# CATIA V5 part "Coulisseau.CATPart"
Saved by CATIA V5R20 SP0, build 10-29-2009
Part number: Coulisseau
Publications: "LongueurCoulisseau"
Bounding box of the stored display mesh (mm): x 16 to 22, y 3.413 to 110, z 34.355 to 85.778
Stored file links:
  C:\Users\Thinkmotion2\Desktop\Pack 1\Retouchés\IAO_2010_1386_abergami\abergami_catiaInitial\ObjetsInitials\Coulisseau.CATPart
  C:\Users\Thinkmotion2\Desktop\Pack 1\Retouchés\IAO_2010_1386_abergami\abergami_catiaInitial\ObjetsInitials\Product2.CATProduct
  C:\Users\Thinkmotion2\Desktop\Pack 1\Retouchés\IAO_2010_1386_abergami\abergami_catiaInitial\ObjetsInitials\NewExcentrique.CATPart
  C:\Users\Thinkmotion2\Desktop\Pack 1\Retouchés\IAO_2010_1386_abergami\abergami_catiaInitial\ObjetsInitials\Squelettedebase.CATPart
  C:\Users\Thinkmotion2\Desktop\Pack 1\Retouchés\IAO_2010_1386_abergami\abergami_catiaInitial\ObjetsInitials\Doigt.CATPart
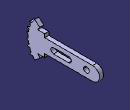
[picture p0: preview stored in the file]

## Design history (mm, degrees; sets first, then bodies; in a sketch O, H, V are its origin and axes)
Parameters
  LongueurCoulisseau = 70 mm
External parameters (linked from other documents)
  External.largeurrainure = 18 mm
  External.EpaisseurCoulisseau = 6 mm
  External.DiametreDoigtExcentrique = 8 mm
  External.DiametreDoigtBati = 8 mm
  External.entraxeDoigtAC = 36 mm
  External.EntraxeAB = 9 mm
Set1
  DatumSurface1: linked copy from another document
  Point1 to Point5: linked copy from another document
Body1 (main body)
  Sketch1 on face of DatumSurface1, origin (16, 0, 0), H (0, 1, 0), V (0, 0, 1)
    arc A1 centre (100, 60) radius 10 from (100, 50) to (100, 70) ccw
    point P1 (100, 60)
    line L1 (100, 70) -> (30, 70)
    point P4 (30, 70)
    line L2 (100, 50) -> (30, 50)
    point P5 (30, 50)
    line L3 (30, 45) -> (30, 50)
    point P6 (30, 45)
    point P7 (30, 75)
    reference projected point E1 (100, 60) from Point3
    reference projected point E2 (100, 60) from Point3
    line L4 (30, 75) -> (20, 75)
    point P8 (20, 75)
    line L5 (30, 45) -> (20, 45)
    point P9 (20, 45)
    arc A2 centre (50, 60) radius 33.541 from (22.7561, 79.5645) to (20, 75) ccw
    line L6 (16.3377, 35.2443) -> (23.1724, 40.9541)
    line L7 (22.7561, 79.5645) -> (15.384, 85.7776)
    arc A3 centre (47.903, 63.6125) radius 33.541 from (20, 45) to (23.1724, 40.9541) ccw
    line L8 (30, 70) -> (30, 75)
    arc A4 centre (45.9702, 60) radius 40 from (15.384, 85.7776) to (11.2225, 79.8141) ccw
    point P14 (45.9702, 60)
    point P15 (15.273, 34.3547)
    line L9 (15.273, 34.3547) -> (16.3377, 35.2443)
    line L10 (6.0167, 58.0706) -> (3.4138, 55.896)
    line L11 (3.4138, 55.896) -> (6.3223, 54.704)
    point P18 (6.3223, 54.704)
    line L12 (6.0354, 62.2833) -> (3.4126, 64.1749)
    point P19 (6.0354, 62.2833)
    line L13 (3.4126, 64.1749) -> (6.3314, 65.3633)
    line L14 (7.0442, 69.2069) -> (4.5538, 72.0604)
    point P22 (7.0442, 69.2069)
    line L15 (4.5538, 72.0604) -> (8.0484, 72.7254)
    line L16 (9.4614, 76.3435) -> (8.0484, 79.8141)
    point P25 (9.4614, 76.3435)
    line L17 (8.0484, 79.8141) -> (11.2225, 79.8141)
    line L18 (7.0442, 50.7931) -> (4.5538, 47.34)
    line L19 (4.5538, 47.34) -> (8.2161, 46.7852)
    point P30 (8.2161, 46.7852)
    line L20 (10.2902, 41.9185) -> (8.0484, 38.81)
    line L21 (8.0484, 38.81) -> (12.044, 38.81)
    point P33 (12.044, 38.81)
    arc A5 centre (45.9702, 60) radius 40 from (12.044, 38.81) to (15.273, 34.3547) ccw
    arc A6 centre (45.9702, 60) radius 40 from (8.2161, 46.7852) to (10.2902, 41.9185) ccw
    arc A7 centre (45.9702, 60) radius 40 from (6.3223, 54.704) to (7.0442, 50.7931) ccw
    arc A8 centre (45.9702, 60) radius 40 from (6.0354, 62.2833) to (6.0167, 58.0706) ccw
    arc A9 centre (45.9702, 60) radius 40 from (7.0442, 69.2069) to (6.3314, 65.3633) ccw
    arc A10 centre (45.9702, 60) radius 40 from (9.4614, 76.3435) to (8.0484, 72.7254) ccw
    distance P5 P6 = 5
    length L1 = 70 {= LongueurCoulisseau}
    radius A1 = 10
    distance E1 L2 = 10
    distance P7 L1 = 5
    distance P1 E2 = 0
    length L5 = 10
    length L2 = 70
    angle L7 L6 = 80
    distance P6 P7 = 30
    distance A2 P4 = 11.1803
    distance P14 L2 = 10
    radius A4 = 40
    horizontal: L1 H, L4 H, L5 H, L17 H, L21 H
    tangency: L2 A1
    vertical: L3 V, L8 V
    coincidence: L3 L8, P14 L7, P14 L6, P15 L6, P18 A4, L11 P6, P19 A4, L12 P6, L13 P7, P22 A4, L15 P8, P25 A4, P30 A4, L19 P9, P33 A4, A4 A5, A4 A6, A4 A7, A4 A8, A4 A9, A4 A10
    parallelism: L9 L6
  Pad1: profile Sketch1, direction (1, 0, 0), length 6 {= External.EpaisseurCoulisseau}
  Sketch2 on end face of Pad1, origin (22, 0, 0), H (0, 1, 0), V (0, 0, 1)
    circle A1 centre (91, 60) radius 4
    point P1 (91, 60)
    reference projected point E1 (91, 60) from Point4
    arc A2 centre (65, 60) radius 4 from (65, 56) to (65, 64) ccw
    point P2 (65, 60)
    arc A3 centre (43, 60) radius 4 from (43, 64) to (43, 56) ccw
    line L1 (65, 64) -> (43, 64)
    line L2 (65, 56) -> (43, 56)
    radius A1 = 4 {= External.DiametreDoigtExcentrique /2}
    distance E1 P1 = 0
    radius A3 = 4 {= External.DiametreDoigtBati /2}
    radius A2 = 4 {= External.DiametreDoigtBati /2}
    length L1 = 22 {= External.EntraxeAB *2+4mm}
    distance P1 P2 = 26 {= External.entraxeDoigtAC - External.EntraxeAB -1mm}
    tangency: L1 A3, L2 A3
  Pocket1: profile Sketch2, direction (-1, 0, 0), through (limit type 6)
